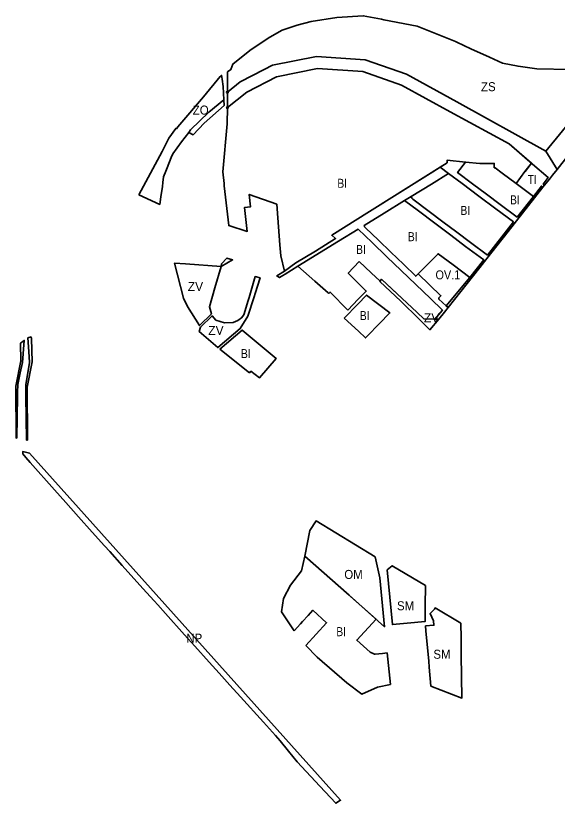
# Model space of a CAD drawing. Extents: x -650276 to -642489, y -1074311 to -1066658.
# Drawn here: x -650276 to -649555, y -1070352 to -1069304 of the extents above; entities that cross this region are included whole.
import ezdxf

# ---------------------------------------------------------------- set-up
doc = ezdxf.new("R2010")
doc.units = 0
doc.header["$LTSCALE"] = 4.8
doc.header["$PDMODE"] = 32
doc.header["$PDSIZE"] = 2.4
for name, color, linetype, lineweight in [('11', 7, 'Continuous', 35), ('12', 7, 'Continuous', 35), ('15', 7, 'Continuous', 35), ('18', 7, 'Continuous', 35), ('2', 7, 'Continuous', 35), ('30', 7, 'Continuous', 35), ('40', 7, 'Continuous', 35), ('41', 7, 'Continuous', 35), ('42', 7, 'Continuous', 35), ('48', 7, 'Continuous', 35)]:
    doc.layers.add(name, color=color, linetype=linetype, lineweight=lineweight)
doc.layers.add('62', color=7, linetype='Continuous')
doc.layers.add('63', color=7, linetype='Continuous')

msp = doc.modelspace()

# ---------------------------------------------------------------- linework, layer by layer
at = {"layer": '11'}
msp.add_lwpolyline([(-649713.73, -1069620.32), (-649713.73, -1069620.32), (-649740.23, -1069647.14), (-649709.94, -1069676.28), (-649712.54, -1069678.98), (-649712.89, -1069679.87), (-649712.51, -1069680.75), (-649703.15, -1069689.75), (-649671.39, -1069651.93), (-649693.63, -1069635.33)], close=True, dxfattribs=at)
at = {"layer": '12'}
msp.add_lwpolyline([(-649891.21, -1070022.68), (-649832.007, -1070074.751), (-649784.87, -1070116.76), (-649791.31, -1070051.51), (-649797.45, -1070023.77), (-649876.31, -1069975.93), (-649884.59, -1069988.57)], close=True, dxfattribs=at)
at = {"layer": '15'}
for points in [[(-649561.17, -1069515.83), (-649555.16, -1069508.07), (-649570.03, -1069483.83), (-649688.625, -1069418.156), (-649755.971, -1069381.179), (-649810.846, -1069362.154), (-649875.434, -1069357.751), (-649934.363, -1069369.537), (-649945.397, -1069375.277), (-649977.239, -1069391.714), (-649994.329, -1069405.451)], [(-649994.293, -1069425.949), (-649968.465, -1069405.189), (-649929.015, -1069384.784), (-649874.391, -1069373.859)], [(-649874.391, -1069373.859), (-649814.067, -1069377.972), (-649762.488, -1069395.854), (-649697.525, -1069431.522), (-649619, -1069474), (-649588, -1069501)], [(-649994.329, -1069405.451), (-649994.329, -1069405.451), (-649994.293, -1069425.949), (-649994.293, -1069425.949)], [(-649710.957, -1069505.107), (-649801.49, -1069561.98), (-649805.22, -1069564.32), (-649855.34, -1069595.8), (-649850.24, -1069600.295), (-649877.129, -1069617.006), (-649903.292, -1069632.541), (-649918.35, -1069643.45), (-649928.67, -1069649.89), (-649924.8, -1069652.19), (-649920.45, -1069649.53), (-649917.38, -1069647.56), (-649900.64, -1069636.78), (-649846.38, -1069603.8), (-649820.02, -1069587.73), (-649801.48, -1069605.57), (-649782.03, -1069624.28), (-649762.85, -1069642.73), (-649743.41, -1069661.43), (-649723.97, -1069680.13), (-649707.985, -1069695.508), (-649717.884, -1069707.295), (-649712.64, -1069707.43), (-649705.28, -1069698.11), (-649700.42, -1069691.8), (-649703.15, -1069689.75), (-649712.51, -1069680.75), (-649712.89, -1069679.87), (-649712.54, -1069678.98), (-649709.94, -1069676.28), (-649740.23, -1069647.14), (-649743.39, -1069650.35), (-649759.97, -1069634.4), (-649776.54, -1069618.46), (-649793.12, -1069602.51), (-649810.49, -1069585.81), (-649811.52, -1069584.44), (-649812.08, -1069582.83)], [(-649722.6, -1069527.61), (-649699.72, -1069513.5), (-649710.957, -1069505.107)], [(-649588, -1069501), (-649567, -1069519), (-649573.922, -1069527.657), (-649571.94, -1069529.24), (-649565.33, -1069521.01), (-649561.17, -1069515.83)], [(-649812.08, -1069582.83), (-649785.72, -1069566.56), (-649758.29, -1069549.64), (-649749.62, -1069544.29), (-649722.6, -1069527.61)]]:
    msp.add_lwpolyline(points, dxfattribs=at)
for points in [[(-650025.31, -1069446.49), (-649998.512, -1069422.926), (-649999.01, -1069415.628), (-650018.873, -1069431.749), (-650043.521, -1069455.69), (-650045.72, -1069459.1), (-650040.012, -1069461.999)], [(-649677.124, -1069610.681), (-649652.88, -1069628.36), (-649671.39, -1069651.93), (-649703.15, -1069689.75), (-649700.42, -1069691.8), (-649658.13, -1069638.84), (-649651.846, -1069630.82), (-649641.978, -1069618.226), (-649620.45, -1069590.75), (-649574.1, -1069531.97), (-649576.071, -1069530.398), (-649586.82, -1069544.11), (-649608.44, -1069571.69), (-649630.88, -1069554.92), (-649649.31, -1069541.16), (-649667.74, -1069527.4), (-649687.77, -1069512.44), (-649677.02, -1069498.32), (-649701.7, -1069495.89), (-649701.57, -1069499.21), (-649710.957, -1069505.107), (-649699.72, -1069513.5), (-649681.7, -1069526.96), (-649659.26, -1069543.71), (-649636.83, -1069560.47), (-649613.37, -1069577.98), (-649628.8, -1069597.67), (-649647.93, -1069622.07), (-649670.34, -1069605.34), (-649688.76, -1069591.57), (-649707.19, -1069577.81), (-649725.62, -1069564.05), (-649747.5, -1069547.71), (-649748.89, -1069546.2), (-649749.62, -1069544.29), (-649758.29, -1069549.64), (-649739.75, -1069563.48), (-649718.13, -1069579.63), (-649696.91, -1069595.47)], [(-650002.39, -1069633.65), (-650002.65, -1069637.14), (-649987.49, -1069628.6), (-649994.913, -1069626.246)]]:
    msp.add_lwpolyline(points, close=True, dxfattribs=at)
for p in [(-649994.329, -1069405.451), (-649994.293, -1069425.949)]:
    msp.add_point(p, dxfattribs=at)
at = {"layer": '18'}
for points in [[(-649781.53, -1070041.2), (-649774.45, -1070113.92), (-649754.82, -1070111.89), (-649731.12, -1070109.96), (-649730.96, -1070094.91), (-649730.89, -1070088.96), (-649730.6, -1070061.98), (-649774.73, -1070035.58)], [(-649730.57, -1070115.76), (-649730, -1070122.01), (-649726.22, -1070162.75), (-649725.49, -1070170.64), (-649723.17, -1070195.81), (-649682.04, -1070211.58), (-649683.12, -1070154.14), (-649682.98, -1070132.1), (-649683.57, -1070112.05), (-649717.72, -1070091.61), (-649718.71, -1070093.35), (-649724.36, -1070099.03), (-649719.69, -1070108.94), (-649719.24, -1070114.87)]]:
    msp.add_lwpolyline(points, close=True, dxfattribs=at)
at = {"layer": '2'}
for points in [[(-649639.18, -1069505.96), (-649637.69, -1069506.15), (-649628.36, -1069513.11), (-649609.93, -1069526.87), (-649598.004, -1069510.814), (-649589.257, -1069499.905), (-649619, -1069474), (-649697.525, -1069431.522), (-649762.488, -1069395.854), (-649814.067, -1069377.972), (-649874.391, -1069373.859), (-649929.015, -1069384.784), (-649968.465, -1069405.189), (-649994.293, -1069425.949), (-649994.53, -1069447.61), (-650000.59, -1069511.15), (-649998.81, -1069527.07), (-649998.5, -1069529.88), (-649992.59, -1069582.88), (-649967.81, -1069590.74), (-649971.38, -1069558.79), (-649963.43, -1069557.91), (-649965.26, -1069541.51), (-649928.48, -1069554.57), (-649927.3, -1069572.44)], [(-649927.3, -1069572.44), (-649924.62, -1069608.53), (-649923.17, -1069623.14), (-649918.35, -1069643.45), (-649918.35, -1069643.45), (-649903.292, -1069632.541), (-649877.129, -1069617.006), (-649850.24, -1069600.295), (-649855.34, -1069595.8), (-649805.22, -1069564.32), (-649801.49, -1069561.98), (-649701.57, -1069499.21), (-649701.7, -1069495.89), (-649677.02, -1069498.32), (-649658.01, -1069500.19), (-649647.45, -1069500.23), (-649638.81, -1069500.26), (-649639.18, -1069505.96)], [(-649677.02, -1069498.32), (-649687.77, -1069512.44), (-649667.74, -1069527.4), (-649649.31, -1069541.16)], [(-649639.18, -1069505.96), (-649638.81, -1069500.26), (-649647.45, -1069500.23), (-649658.01, -1069500.19), (-649677.02, -1069498.32)], [(-649707.19, -1069577.81), (-649688.76, -1069591.57), (-649670.34, -1069605.34), (-649647.93, -1069622.07), (-649628.8, -1069597.67), (-649613.37, -1069577.98), (-649636.83, -1069560.47), (-649659.26, -1069543.71), (-649681.7, -1069526.96), (-649699.72, -1069513.5), (-649722.6, -1069527.61), (-649749.62, -1069544.29)], [(-649609.93, -1069526.87), (-649628.36, -1069513.11), (-649637.69, -1069506.15), (-649639.18, -1069505.96)], [(-649649.31, -1069541.16), (-649630.88, -1069554.92), (-649608.44, -1069571.69), (-649586.82, -1069544.11), (-649609.93, -1069526.87)], [(-649749.62, -1069544.29), (-649748.89, -1069546.2), (-649747.5, -1069547.71), (-649725.62, -1069564.05), (-649707.19, -1069577.81)], [(-649758.29, -1069549.64), (-649785.72, -1069566.56), (-649812.08, -1069582.83)], [(-649671.39, -1069651.93), (-649652.88, -1069628.36), (-649677.124, -1069610.681), (-649696.91, -1069595.47), (-649718.13, -1069579.63), (-649739.75, -1069563.48), (-649758.29, -1069549.64)], [(-649788.91, -1069654.4), (-649781.09, -1069661.69), (-649761.34, -1069680.08), (-649741.61, -1069698.46), (-649732.52, -1069706.92), (-649717.884, -1069707.295), (-649707.985, -1069695.508), (-649723.97, -1069680.13), (-649743.41, -1069661.43), (-649762.85, -1069642.73), (-649782.03, -1069624.28), (-649801.48, -1069605.57), (-649820.02, -1069587.73), (-649846.38, -1069603.8), (-649900.64, -1069636.78)], [(-649812.08, -1069582.83), (-649811.52, -1069584.44), (-649810.49, -1069585.81), (-649793.12, -1069602.51), (-649776.54, -1069618.46), (-649759.97, -1069634.4)], [(-649740.23, -1069647.14), (-649713.73, -1069620.32), (-649713.73, -1069620.32), (-649693.63, -1069635.33), (-649671.39, -1069651.93)], [(-649833.94, -1069695.239), (-649819.98, -1069680.92), (-649809.47, -1069670.13), (-649833.38, -1069646.08), (-649818.71, -1069630.64)], [(-649818.71, -1069630.64), (-649802.9, -1069645.96), (-649791, -1069657), (-649788.91, -1069654.4)], [(-649900.64, -1069636.78), (-649877.82, -1069656.83), (-649859.96, -1069672.53)], [(-649759.97, -1069634.4), (-649743.39, -1069650.35), (-649740.23, -1069647.14)], [(-649859.96, -1069672.53), (-649859.17, -1069673.22), (-649857.49, -1069671.46), (-649833.94, -1069695.239)], [(-649905.51, -1070122.35), (-649922.3, -1070096.9), (-649919.55, -1070079.01), (-649910.34, -1070061.29), (-649895.45, -1070042.15), (-649891.21, -1070022.68), (-649796.4, -1070106.56)], [(-649796.4, -1070106.56), (-649891.21, -1070022.68), (-649895.45, -1070042.15), (-649910.34, -1070061.29), (-649919.55, -1070079.01), (-649922.3, -1070096.9), (-649905.51, -1070122.35)], [(-649894.095, -1070109.853), (-649886.83, -1070101.89), (-649880.42, -1070094.87), (-649862.22, -1070111.54), (-649889.87, -1070141.83)], [(-649905.51, -1070122.35), (-649897.03, -1070113.07), (-649894.095, -1070109.853)], [(-649804.29, -1070150.68), (-649821.97, -1070134.58), (-649796.4, -1070106.56)], [(-649781.433, -1070151.59), (-649777.29, -1070193.57), (-649794.37, -1070197.2), (-649815.33, -1070206.63), (-649835.28, -1070191.27), (-649874.94, -1070157.19), (-649889.87, -1070141.83)], [(-649889.87, -1070141.83), (-649874.94, -1070157.19), (-649835.28, -1070191.27), (-649815.33, -1070206.63), (-649794.37, -1070197.2)], [(-649781.436, -1070151.591), (-649787.92, -1070152.23), (-649797.33, -1070153.41), (-649798.33, -1070153.32), (-649799.29, -1070153), (-649804.29, -1070150.68)], [(-649794.37, -1070197.2), (-649777.29, -1070193.57), (-649781.433, -1070151.59)]]:
    msp.add_lwpolyline(points, dxfattribs=at)
for points in [[(-649838.99, -1069706.15), (-649820.64, -1069687.33), (-649808.96, -1069675.34), (-649777.94, -1069699.2), (-649792.13, -1069713.65), (-649807.66, -1069729.46), (-649810.41, -1069732.28), (-649819.9, -1069723.61)], [(-650004.59, -1069747.27), (-649974.86, -1069721.96), (-649966.52, -1069728.87), (-649929.38, -1069759.65), (-649951.56, -1069785.42), (-649963, -1069776.7), (-649965, -1069778.7)]]:
    msp.add_lwpolyline(points, close=True, dxfattribs=at)
at = {"layer": '30'}
for points in [[(-649571.94, -1069529.24), (-649573.922, -1069527.657), (-649567, -1069519), (-649588, -1069501), (-649589.257, -1069499.905), (-649597.935, -1069510.728)], [(-649597.997, -1069510.805), (-649598.004, -1069510.814), (-649609.93, -1069526.87), (-649586.82, -1069544.11)], [(-649597.935, -1069510.728), (-649597.763, -1069510.865), (-649597.997, -1069510.805)], [(-649586.82, -1069544.11), (-649576.071, -1069530.398), (-649574.1, -1069531.97), (-649571.94, -1069529.24)]]:
    msp.add_lwpolyline(points, dxfattribs=at)
at = {"layer": '40'}
for points in [[(-650002.65, -1069637.14), (-650050.26, -1069633.65), (-650064.77, -1069633.06), (-650052.88, -1069679.49), (-650047.45, -1069690.69), (-650031.64, -1069715.9), (-650015.53, -1069700.21), (-650018.31, -1069690.89), (-650011.15, -1069665.82)], [(-649998, -1069712.26), (-650009.509, -1069708.678), (-650014.74, -1069702.9), (-650030.26, -1069717.96), (-650032.13, -1069723.75), (-650010.04, -1069742.58), (-650006.85, -1069745.3), (-649977.31, -1069720.05), (-649967.27, -1069703.29), (-649958.87, -1069677.59), (-649957.54, -1069673.5), (-649950.69, -1069652.54), (-649957.15, -1069650.76), (-649965.45, -1069678.6), (-649966.59, -1069682.44), (-649972.35, -1069701.78), (-649975.45, -1069705.65), (-649980.22, -1069709.07), (-649986.69, -1069712.03)], [(-649738.93, -1069707.42), (-649724.51, -1069721.57), (-649712.64, -1069707.43), (-649732.52, -1069706.92), (-649741.61, -1069698.46), (-649788.91, -1069654.4), (-649791.3, -1069657.21), (-649763.31, -1069683.5)]]:
    msp.add_lwpolyline(points, close=True, dxfattribs=at)
at = {"layer": '41'}
msp.add_lwpolyline([(-649537.32, -1069375.23), (-649582.25, -1069374.51), (-649607.18, -1069370.92), (-649627.76, -1069366.8), (-649645.03, -1069358.8), (-649670.23, -1069347.9), (-649688.73, -1069338.7), (-649690.59, -1069337.98), (-649741.5, -1069317.74), (-649785.8, -1069308.94), (-649789, -1069308.31), (-649813.3, -1069303.66), (-649848.62, -1069305.95), (-649882.93, -1069311.1), (-649901.58, -1069316.01), (-649921.54, -1069323.03), (-649922.11, -1069323.35), (-649939.81, -1069333.47), (-649964.53, -1069350.02), (-649987.12, -1069368.03), (-649989.67, -1069375.36), (-649994.38, -1069378.33), (-649994.35, -1069394.43), (-649994.34, -1069398.8), (-649994.329, -1069405.451), (-649977.239, -1069391.714), (-649945.397, -1069375.277), (-649934.363, -1069369.537), (-649875.434, -1069357.751), (-649810.846, -1069362.154), (-649755.971, -1069381.179), (-649688.625, -1069418.156), (-649570.03, -1069483.83), (-649499.761, -1069397.905)], dxfattribs=at)
at = {"layer": '42'}
msp.add_lwpolyline([(-650112.18, -1069542.11), (-650081.29, -1069484.35), (-650072.5, -1069466.44), (-650063.12, -1069453.54), (-650062.17, -1069454.05), (-650060.29, -1069451.7), (-650057.49, -1069448.18), (-650026.33, -1069411.47), (-650003.73, -1069384.71), (-650002.11, -1069382.8), (-650001.13, -1069388.13), (-649999.95, -1069397.98), (-649999.01, -1069415.628), (-650018.873, -1069431.749), (-650043.521, -1069455.69), (-650045.72, -1069459.1), (-650055.612, -1069471.639), (-650066.897, -1069487.541), (-650069.369, -1069492.132), (-650074.75, -1069506.133), (-650076.365, -1069510.333), (-650079.264, -1069517.874), (-650080.302, -1069525.418), (-650080.802, -1069530.768), (-650082.963, -1069544.736), (-650084.345, -1069554.773)], close=True, dxfattribs=at)
at = {"layer": '48'}
for points in [[(-649555.16, -1069508.07), (-649540.81, -1069490.25), (-649513.66, -1069456.53), (-649510.56, -1069452.67), (-649498.47, -1069437.65), (-649424.8, -1069346.14)], [(-649499.761, -1069397.905), (-649570.03, -1069483.83), (-649555.16, -1069508.07)]]:
    msp.add_lwpolyline(points, dxfattribs=at)
for points in [[(-650270.059, -1069739.232), (-650269.449, -1069762.714), (-650276.214, -1069796.532), (-650275.76, -1069865.474), (-650274.95, -1069865.62), (-650273.87, -1069809.74), (-650273.78, -1069805.2), (-650273.58, -1069794.48), (-650270.15, -1069778.65), (-650267.22, -1069765.1), (-650265.37, -1069741.61), (-650264.91, -1069735.69)], [(-650260.645, -1069868.536), (-650260.748, -1069867.327), (-650261.204, -1069797.969), (-650254.411, -1069764.006), (-650255.21, -1069733.253), (-650255.716, -1069731.162), (-650259.97, -1069732.29), (-650258.74, -1069750.62), (-650257.77, -1069765.2), (-650262.93, -1069794.84), (-650262.77, -1069805.54), (-650262.7, -1069809.89), (-650261.8, -1069868.33)], [(-650257.713, -1069885.547), (-650266.89, -1069883.7), (-650266.68, -1069886.78), (-650262.64, -1069891.57), (-650257.16, -1069898.07), (-650224.71, -1069934.41), (-650209.51, -1069951.43), (-650192.51, -1069970.47), (-650174.3, -1069990.86), (-650157.87, -1070009.26), (-650151.03, -1070016.84), (-650134.26, -1070035.45), (-650106.76, -1070065.96), (-650091.89, -1070082.46), (-650087.18, -1070087.68), (-650076.72, -1070099.29), (-650051.33, -1070127.45), (-650037.78, -1070142.48), (-650018.41, -1070163.97), (-650005.3, -1070178.51), (-649990.95, -1070194.43), (-649977.05, -1070209.85), (-649946.39, -1070243.87), (-649930.46, -1070261.54), (-649924.15, -1070268.55), (-649913.03, -1070282.44), (-649901.59, -1070296.73), (-649871.28, -1070329.01), (-649850.04, -1070351.64), (-649843.513, -1070347.685)]]:
    msp.add_lwpolyline(points, close=True, dxfattribs=at)

# ---------------------------------------------------------------- texts
at = {"layer": '62'}
for s, width, p in [('ZS', 0.95, (-649656.482, -1069404.05)), ('ZO', 0.95, (-650040.423, -1069435.188)), ('BI', 0.85, (-649847.88, -1069532.658)), ('BI', 0.85, (-649817.88, -1069708.658)), ('BI', 0.85, (-649976.221, -1069759.292)), ('OM', 0.95, (-649838.604, -1070053.132)), ('SM', 0.95, (-649768.411, -1070094.846)), ('BI', 0.85, (-649849.221, -1070129.292)), ('NP', 0.95, (-650048.985, -1070137.967)), ('SM', 0.95, (-649719.964, -1070159.337))]:
    msp.add_text(s, height=12, dxfattribs=dict(at, width=width)).set_placement(p)
for p in [(-650047.124, -1069669.988), (-650019.82, -1069728.32)]:
    msp.add_text('ZV', height=12, dxfattribs=at).set_placement(p)
at = {"layer": '63'}
for s, width, p in [('TI', 0.85, (-649594.476, -1069527.535)), ('BI', 0.85, (-649617.88, -1069554.658)), ('BI', 0.85, (-649683.88, -1069568.658)), ('BI', 0.85, (-649753.88, -1069603.658)), ('BI', 0.85, (-649822.88, -1069620.658)), ('OV.1', 0.9, (-649717.147, -1069654.487))]:
    msp.add_text(s, height=12, dxfattribs=dict(at, width=width)).set_placement(p)
msp.add_text('ZV', height=12, dxfattribs=at).set_placement((-649732.572, -1069711.498))

doc.saveas('drawing.dxf')
